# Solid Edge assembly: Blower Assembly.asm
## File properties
Author: CADCIM
Template: NORMENG.ASM
Last saved by: CADCIM
Revision: 11
Application: Solid Edge
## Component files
Lower Housing.par
upper housing.par
Blower.par
cover.par
motorshaft.par
Motor.par
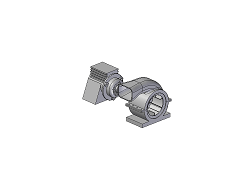
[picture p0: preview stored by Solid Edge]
